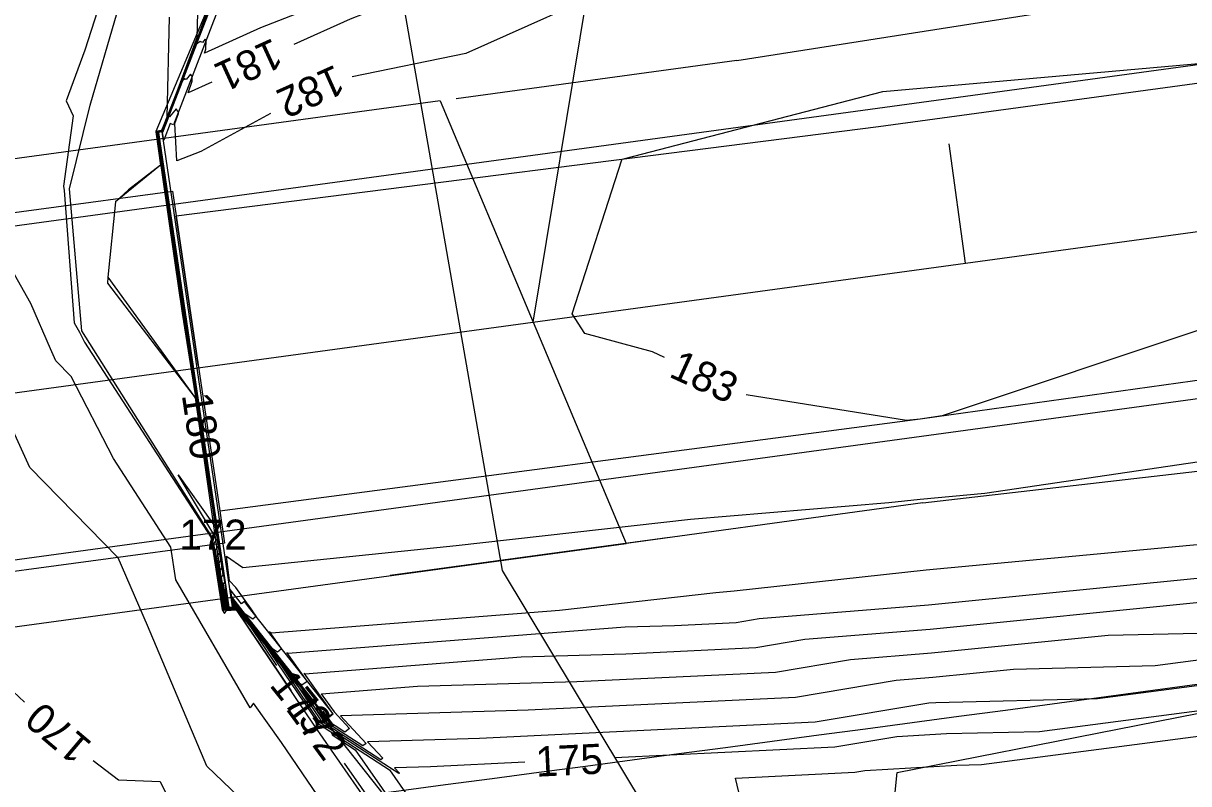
# Model space of a CAD drawing. Extents: x 2086416 to 2115205, y 575507 to 632762.
# Drawn here: x 2111557.3 to 2111634.8, y 581629.5 to 581680.1 of the extents above; entities that cross this region are included whole.
import ezdxf

# ---------------------------------------------------------------- set-up
doc = ezdxf.new("R2010")
doc.units = 0
for name, color, linetype in [('DTM Contours Major', 7, 'Continuous'), ('DTM Contours Major Text', 7, 'Continuous'), ('DTM Contours Minor', 7, 'Continuous'), ('DTM Contours Minor Text', 7, 'Continuous'), ('Exist Hydro Stream or Body of Water', 7, 'Continuous'), ('Exist Hydrographic Stream Bed', 7, 'Continuous'), ('Exist Right of Way Line', 7, 'Continuous'), ('Exist Roads EOP', 7, 'Continuous'), ('Exist Structure Major Bridge WW', 7, 'Continuous'), ('Exist Structure Major Deck Tunnel Box Culvert', 7, 'Continuous'), ('Exist Vegetation Woods Line', 7, 'Continuous'), ('Prop EOT', 7, 'Continuous'), ('Prop Horizontal Alignment', 7, 'Continuous'), ('Prop Horizontal Alignment Station Label', 7, 'Continuous'), ('Prop Horizontal Alignment Tick Large', 7, 'Continuous'), ('Prop Paved Shoulder', 7, 'Continuous'), ('Prop Roadway Bridge', 7, 'Continuous'), ('Prop SS Cut Line', 7, 'Continuous')]:
    doc.layers.add(name, color=color, linetype=linetype)

msp = doc.modelspace()

# ---------------------------------------------------------------- linework, layer by layer
at = {"layer": 'DTM Contours Major'}
for points in [[(2111577.062, 581633.567), (2111574.13, 581637.914), (2111571.386, 581641.335), (2111571.409, 581641.143), (2111571.336, 581641.132), (2111570.733, 581641.093), (2111570.186, 581644.597), (2111570.364, 581644.847), (2111569.098, 581653.407), (2111567.724, 581662.01), (2111566.227, 581672.465), (2111566.165, 581672.886), (2111566.466, 581672.935), (2111566.521, 581672.943), (2111566.528, 581672.934), (2111568.39, 581677.722), (2111570.775, 581684.171)], [(2111580.165, 581682.557), (2111573.082, 581679.801), (2111569.362, 581678.106), (2111569.457, 581678.372), (2111569.468, 581678.954), (2111569.404, 581679.039), (2111569.226, 581678.826), (2111569.08, 581678.891), (2111568.834, 581678.698), (2111566.565, 581672.861), (2111566.542, 581672.893), (2111566.359, 581672.866), (2111566.259, 581672.849), (2111566.467, 581671.443), (2111566.966, 581667.96), (2111567.423, 581665.095), (2111568.733, 581656.242)], [(2111563.624, 581644.535), (2111557.765, 581650.557), (2111554.83, 581656.943), (2111553.167, 581660.831), (2111550.584, 581662.207), (2111544.629, 581660.993), (2111538.463, 581666.005), (2111535.965, 581667.83), (2111530.949, 581672.288), (2111530.521, 581672.558), (2111527.53, 581672.834), (2111528.703, 581670.603), (2111528.883, 581668.916), (2111534.119, 581665.006), (2111537.381, 581653.906), (2111537.496, 581653.447), (2111544.432, 581648.303), (2111549.461, 581642.401), (2111557.401, 581634.942)], [(2111569.612, 581650.307), (2111570.775, 581642.449), (2111570.715, 581642.365), (2111570.897, 581641.201), (2111571.098, 581641.214), (2111571.287, 581641.242), (2111571.228, 581641.744)], [(2111571.228, 581641.744), (2111575.652, 581636.227), (2111575.847, 581636.099), (2111575.905, 581636.144), (2111576.193, 581636.349), (2111574.837, 581638.252), (2111574.911, 581638.195), (2111597.323, 581639.951), (2111600.607, 581640.048), (2111604.699, 581640.246), (2111606.241, 581640.505), (2111617.499, 581641.405), (2111642.062, 581643.861), (2111644.096, 581643.911), (2111647.513, 581644.36), (2111664.381, 581646.045)], [(2111561.972, 581631.067), (2111563.648, 581629.772), (2111566.428, 581629.67), (2111574.697, 581612.578), (2111574.966, 581612.195), (2111584.328, 581609.029), (2111586.691, 581607.388), (2111582.492, 581616.152), (2111576.474, 581624.007), (2111569.516, 581630.68), (2111565.57, 581640.043), (2111563.624, 581644.535)], [(2111696.049, 581641.363), (2111672.077, 581638.811), (2111669.843, 581638.828), (2111651.777, 581636.424), (2111648.999, 581636.147), (2111624.869, 581632.976), (2111618.681, 581632.825), (2111615.387, 581632.634), (2111611.27, 581631.941), (2111596.647, 581631.235)], [(2111590.654, 581630.945), (2111584.392, 581630.643), (2111581.999, 581630.572), (2111582.326, 581630.219), (2111582.283, 581630.187), (2111577.062, 581633.567)]]:
    msp.add_lwpolyline(points, dxfattribs=at)
at = {"layer": 'DTM Contours Minor'}
for points in [[(2111554.563, 581717.65), (2111557.36, 581715.394), (2111558.77, 581713.514), (2111570.458, 581698.119), (2111560.752, 581706.535), (2111561.783, 581697.351), (2111565.987, 581692.592), (2111561.42, 581678.299), (2111560.172, 581674.931), (2111560.629, 581673.945), (2111559.995, 581669.266), (2111560.03, 581668.962), (2111560.707, 581660.161), (2111561.06, 581659.542), (2111561.396, 581658.891), (2111569.796, 581645.905), (2111570.547, 581641.087), (2111570.686, 581640.847), (2111570.828, 581641.041), (2111571.479, 581641.083), (2111571.482, 581641.083), (2111571.481, 581641.089), (2111571.569, 581640.98), (2111575.135, 581635.693)], [(2111771.48, 581708.935), (2111760.551, 581707.387), (2111751.324, 581706.065), (2111741.049, 581703.184), (2111726.364, 581703.031), (2111711.255, 581700.898), (2111699.308, 581700.058), (2111691.644, 581698.037), (2111679.979, 581697.458), (2111663.055, 581697.517), (2111661.641, 581697.308), (2111661.538, 581697.284), (2111642.179, 581694.795), (2111641.925, 581694.737), (2111612.432, 581690.93), (2111612.349, 581690.915), (2111598.441, 581688.663), (2111596.352, 581688.299), (2111593.432, 581686.787), (2111582.067, 581681.437), (2111581.765, 581681.432), (2111579.054, 581680.377), (2111575.311, 581678.672)], [(2111775.952, 581702.182), (2111765.879, 581701.692), (2111760.907, 581700.977), (2111757.858, 581700.672), (2111741.952, 581696.212), (2111712.843, 581695.908), (2111712.055, 581695.797), (2111711.432, 581695.753), (2111692.466, 581690.751), (2111663.596, 581689.317), (2111662.082, 581689.322), (2111660.385, 581689.117), (2111642.993, 581686.483), (2111626.562, 581686.502), (2111613.936, 581684.954), (2111604.265, 581685.115), (2111597.651, 581682.972), (2111586.742, 581678.077), (2111579.19, 581676.523)], [(2111569.01, 581685.022), (2111568.855, 581679.129), (2111567.524, 581675.529), (2111566.521, 581672.948), (2111566.517, 581672.953), (2111566.487, 581672.949), (2111566.146, 581672.893), (2111566.179, 581672.67), (2111567.876, 581660.82), (2111569.433, 581651.069), (2111570.282, 581645.327), (2111570.08, 581645.043), (2111570.701, 581641.072), (2111571.384, 581641.115), (2111571.433, 581641.123), (2111571.418, 581641.253), (2111573.276, 581638.936), (2111576.945, 581633.496), (2111581.656, 581630.446), (2111583.793, 581627.386), (2111584.244, 581626.917), (2111585.478, 581625.384)], [(2111577.178, 581633.638), (2111574.983, 581636.892), (2111571.354, 581641.416), (2111571.385, 581641.163), (2111571.288, 581641.148), (2111570.766, 581641.115), (2111570.292, 581644.15), (2111570.446, 581644.368), (2111568.763, 581655.744), (2111567.573, 581663.2), (2111566.275, 581672.261), (2111566.184, 581672.878), (2111566.444, 581672.921), (2111566.525, 581672.933), (2111566.535, 581672.919), (2111569.255, 581679.915), (2111570.799, 581684.09)], [(2111577.411, 581633.781), (2111576.691, 581634.848), (2111571.291, 581641.58), (2111571.336, 581641.203), (2111571.193, 581641.181), (2111570.832, 581641.158), (2111570.504, 581643.258), (2111570.611, 581643.408), (2111568.093, 581660.42), (2111567.269, 581665.58), (2111566.371, 581671.852), (2111566.221, 581672.864), (2111566.402, 581672.893), (2111566.534, 581672.913), (2111566.55, 581672.89), (2111570.691, 581683.54)], [(2111577.294, 581633.709), (2111575.837, 581635.87), (2111571.323, 581641.498), (2111571.36, 581641.183), (2111571.241, 581641.165), (2111570.799, 581641.136), (2111570.398, 581643.704), (2111570.529, 581643.888), (2111568.428, 581658.082), (2111567.421, 581664.39), (2111566.323, 581672.056), (2111566.203, 581672.871), (2111566.423, 581672.907), (2111566.53, 581672.923), (2111566.543, 581672.905), (2111570.121, 581682.109)], [(2111576.272, 581682.839), (2111573.71, 581682.421), (2111570.375, 581681.023), (2111570.381, 581681.335), (2111570.364, 581681.358), (2111570.316, 581681.3), (2111570.109, 581681.392), (2111569.763, 581681.119), (2111566.558, 581672.876), (2111566.538, 581672.903), (2111566.381, 581672.879), (2111566.24, 581672.856), (2111566.419, 581671.647), (2111567.118, 581666.77), (2111567.758, 581662.757), (2111570.693, 581642.928), (2111570.61, 581642.812), (2111570.865, 581641.18), (2111571.145, 581641.198), (2111571.312, 581641.222), (2111571.26, 581641.662)], [(2111567.025, 581680.498), (2111566.851, 581673.856), (2111566.658, 581673.336), (2111566.513, 581672.963), (2111566.513, 581672.963), (2111566.508, 581672.963), (2111566.127, 581672.9), (2111566.131, 581672.874), (2111566.449, 581670.656), (2111564.307, 581669.018), (2111563.443, 581668.224), (2111562.943, 581663.213), (2111562.927, 581662.803), (2111568.739, 581655.173), (2111569.767, 581648.731), (2111570.2, 581645.807), (2111569.974, 581645.489), (2111570.668, 581641.05), (2111571.432, 581641.099), (2111571.457, 581641.103), (2111571.449, 581641.171), (2111572.422, 581639.958), (2111574.154, 581637.391)], [(2111643.847, 581677.764), (2111644.952, 581677.932), (2111662.194, 581679.764), (2111662.971, 581679.587), (2111663.56, 581679.562), (2111683.069, 581679.032), (2111693.952, 581679.325), (2111701.93, 581679.257), (2111713.811, 581679.697), (2111722.926, 581678.431), (2111717.299, 581676.654), (2111714.292, 581675.929), (2111711.547, 581675.446), (2111695.04, 581672.327), (2111687.453, 581670.987), (2111665.531, 581666.866), (2111655.863, 581664.226), (2111646.097, 581662.087), (2111636.124, 581659.903), (2111618.397, 581653.989), (2111616.941, 581653.759), (2111616.037, 581653.667), (2111605.38, 581655.386)], [(2111599.933, 581657.871), (2111599.142, 581658.247), (2111594.644, 581659.471), (2111593.813, 581660.769), (2111597.108, 581671.011), (2111597.122, 581671.059), (2111597.229, 581671.081), (2111597.239, 581671.086), (2111597.297, 581671.105), (2111614.462, 581675.567), (2111639.449, 581677.769), (2111643.847, 581677.764)], [(2111569.851, 581676.185), (2111568.274, 581675.467), (2111568.549, 581676.238), (2111568.556, 581676.573), (2111568.444, 581676.72), (2111568.136, 581676.352), (2111568.05, 581676.39), (2111567.906, 581676.276), (2111566.572, 581672.847), (2111566.547, 581672.883), (2111566.338, 581672.852), (2111566.278, 581672.842), (2111566.515, 581671.238), (2111566.814, 581669.15), (2111567.088, 581667.433), (2111570.857, 581641.969), (2111570.821, 581641.919), (2111570.93, 581641.223), (2111571.05, 581641.231), (2111571.263, 581641.262), (2111571.196, 581641.825)], [(2111573.759, 581674.096), (2111569.118, 581671.56), (2111567.528, 581670.942), (2111567.402, 581673.431), (2111567.641, 581674.104), (2111567.643, 581674.192), (2111567.484, 581674.402), (2111567.046, 581673.878), (2111567.021, 581673.889), (2111566.978, 581673.855), (2111566.58, 581672.832), (2111566.551, 581672.873), (2111566.317, 581672.838), (2111566.297, 581672.835), (2111566.563, 581671.034), (2111566.662, 581670.341), (2111566.753, 581669.77), (2111570.939, 581641.489), (2111570.927, 581641.473), (2111570.963, 581641.244), (2111571.002, 581641.247), (2111571.239, 581641.282), (2111571.165, 581641.907)], [(2111598.535, 581596.664), (2111585.912, 581617.09), (2111584.535, 581618.974), (2111576.895, 581628.719), (2111574.477, 581632.249), (2111572.617, 581634.865), (2111572.402, 581634.572), (2111567.467, 581643.071), (2111567.127, 581645.256), (2111563.317, 581651.146), (2111560.505, 581656.601), (2111559.492, 581657.643), (2111559.123, 581658.446), (2111557.832, 581661.464), (2111555.517, 581665.512)], [(2111571.165, 581641.907), (2111571.996, 581640.87), (2111572.571, 581640.492), (2111572.743, 581640.626), (2111572.795, 581640.663), (2111572.546, 581641.013), (2111572.584, 581640.984), (2111571.455, 581642.576), (2111571.032, 581643.012), (2111570.823, 581644.648), (2111571.916, 581643.904), (2111586.094, 581645.355), (2111601.664, 581647.121), (2111614.846, 581648.211), (2111616.947, 581648.442), (2111621.236, 581648.843), (2111646.92, 581652.625), (2111665.944, 581653.445), (2111667.701, 581653.608), (2111692.097, 581649.43)], [(2111569.975, 581646.085), (2111567.608, 581650.059), (2111569.849, 581646.913), (2111570.065, 581646.63), (2111570.102, 581646.394), (2111570.118, 581646.287), (2111569.975, 581646.085)], [(2111571.196, 581641.825), (2111573.824, 581638.549), (2111574.209, 581638.295), (2111574.324, 581638.385), (2111574.494, 581638.506), (2111573.692, 581639.632), (2111573.792, 581639.556), (2111592.953, 581641.057), (2111603.347, 581642.235), (2111604.567, 581642.336), (2111617.335, 581643.741), (2111643.391, 581646.181), (2111647.216, 581646.744), (2111650.05, 581646.866), (2111668.074, 581648.539), (2111670.919, 581648.052), (2111693.464, 581647.881)], [(2111571.26, 581641.662), (2111577.48, 581633.906), (2111577.485, 581633.903), (2111577.486, 581633.904), (2111577.892, 581634.191), (2111575.982, 581636.871), (2111576.03, 581636.835), (2111590.423, 581637.963), (2111597.364, 581638.167), (2111606.013, 581638.585), (2111609.271, 581639.133), (2111617.594, 581639.798), (2111635.752, 581641.614), (2111640.25, 581641.724), (2111647.81, 581642.717), (2111662.919, 581644.226), (2111668.671, 581644.992), (2111686.335, 581644.858)], [(2111671.884, 581640.351), (2111669.55, 581640.369), (2111654.563, 581638.375), (2111648.702, 581637.79), (2111628.715, 581635.163), (2111617.979, 581634.901), (2111617.512, 581634.874), (2111609.956, 581633.602), (2111587.635, 581632.524), (2111580.203, 581632.305), (2111581.22, 581631.207), (2111581.086, 581631.108), (2111577.178, 581633.638)], [(2111638.154, 581639.767), (2111636.405, 581639.537), (2111629.442, 581639.367), (2111617.689, 581638.192), (2111612.302, 581637.761), (2111607.327, 581636.924), (2111594.121, 581636.286), (2111583.523, 581635.974), (2111577.149, 581635.474), (2111577.128, 581635.491), (2111577.984, 581634.288), (2111579.007, 581633.185), (2111578.692, 581632.951), (2111577.411, 581633.781)], [(2111655.217, 581640.113), (2111648.405, 581639.432), (2111632.56, 581637.35), (2111623.132, 581637.12), (2111617.784, 581636.585), (2111615.332, 581636.39), (2111608.642, 581635.263), (2111590.878, 581634.405), (2111578.406, 581634.038), (2111580.113, 581632.196), (2111579.889, 581632.029), (2111577.294, 581633.709)], [(2111589.242, 581620.711), (2111589.877, 581619.921), (2111590.857, 581618.927), (2111592.405, 581618.486), (2111599.33, 581615.104), (2111605.372, 581623.887), (2111605.711, 581625.528), (2111604.66, 581629.897), (2111612.584, 581630.28), (2111613.262, 581630.394), (2111619.383, 581630.749), (2111621.024, 581630.789), (2111642.89, 581633.662), (2111647.196, 581633.15), (2111648.463, 581631.541), (2111653.203, 581633.039), (2111670.864, 581631.971), (2111682.196, 581631.349), (2111685.064, 581615.457), (2111702.133, 581615.465), (2111706.656, 581602.934), (2111726.967, 581593.524), (2111719.652, 581583.63), (2111725.706, 581574.006)], [(2111577.85, 581632.764), (2111579.379, 581631.774), (2111585.586, 581622.885), (2111586.895, 581621.522), (2111588.77, 581619.193), (2111592.833, 581615.071), (2111599.247, 581613.245), (2111610.211, 581607.891), (2111612.256, 581606.571), (2111617.699, 581603.706), (2111619.118, 581601.942), (2111619.518, 581603.35), (2111619.215, 581603.582), (2111621.458, 581611.664), (2111622.113, 581614.012), (2111639.991, 581603.538), (2111640.806, 581603.356), (2111642.077, 581602.394), (2111666.164, 581595.53), (2111674.849, 581575.034)], [(2111578.656, 581630.876), (2111587.378, 581618.383), (2111587.912, 581617.828), (2111588.893, 581616.777), (2111596.136, 581605.984), (2111600.862, 581598.818)]]:
    msp.add_lwpolyline(points, dxfattribs=at)
at = {"layer": 'Exist Hydro Stream or Body of Water'}
msp.add_lwpolyline([(2111621.041, 581592.195), (2111611.64, 581604.325), (2111605.912, 581608.14), (2111600.475, 581607.014), (2111602.119, 581600.097), (2111601.107, 581599.205), (2111587.776, 581617.384), (2111576.692, 581633.341), (2111571.484, 581641.081), (2111570.636, 581641.029), (2111569.871, 581645.923), (2111561.21, 581659.642), (2111560.398, 581669.08), (2111561.77, 581674.655), (2111567.139, 581693.151), (2111571.775, 581696.534), (2111557.095, 581714.198)], dxfattribs=at)
at = {"layer": 'Exist Hydrographic Stream Bed'}
msp.add_lwpolyline([(2112129.652, 582477.712), (2111835.899, 582368.961), (2111727.147, 582231.15), (2111672.647, 582129.589), (2111610.896, 582009.957), (2111585.646, 581897.526), (2111574.646, 581806.895), (2111574.646, 581727.084), (2111582.896, 581679.524), (2111589.146, 581643.704), (2111621.896, 581589.333), (2111665.397, 581516.772), (2111701.647, 581379.011), (2111737.898, 581248.45), (2111785.148, 581103.388)], dxfattribs=at)
at = {"layer": 'Exist Right of Way Line'}
msp.add_arc((2108326.546, 606231.499), 24816.937, 277.3939111, 277.8562149, dxfattribs=at)
at = {"layer": 'Exist Roads EOP'}
for points in [[(2111568.946, 581657.382), (2111567.482, 581667.278), (2111614.169, 581673.234), (2111663.501, 581679.942), (2111712.967, 581686.457), (2111762.009, 581693.34), (2111810.989, 581700.16), (2111860.082, 581706.99), (2111909.436, 581713.775), (2111958.293, 581720.29), (2112007.473, 581726.809), (2112052.556, 581733.019), (2112053.866, 581723.651)], [(2111568.946, 581657.382), (2111567.482, 581667.278), (2111614.169, 581673.234), (2111663.501, 581679.942), (2111712.967, 581686.457), (2111762.009, 581693.34), (2111810.989, 581700.16), (2111860.082, 581706.99), (2111909.436, 581713.775), (2111958.293, 581720.29), (2112007.473, 581726.809), (2112052.556, 581733.019), (2112053.866, 581723.651)], [(2111568.946, 581657.382), (2111570.384, 581647.665), (2111616.941, 581653.786), (2111666.479, 581660.703), (2111715.395, 581667.634), (2111764.576, 581674.503), (2111813.386, 581681.192), (2111862.599, 581687.866), (2111911.635, 581694.622), (2111960.562, 581701.229), (2112009.92, 581707.698), (2112055.279, 581713.547), (2112053.866, 581723.651)]]:
    msp.add_lwpolyline(points, dxfattribs=at)
at = {"layer": 'Exist Structure Major Bridge WW'}
for points in [[(2111566.583, 581672.826), (2111566.849, 581673.52), (2111570.25, 581682.39), (2111570.844, 581683.94), (2111571.077, 581683.851), (2111570.483, 581682.3), (2111570.717, 581682.211), (2111567.316, 581673.341), (2111567.082, 581673.43), (2111566.658, 581672.322), (2111566.583, 581672.826)], [(2111566.553, 581672.868), (2111566.306, 581672.831), (2111570.979, 581641.255), (2111571.227, 581641.292), (2111566.553, 581672.868)], [(2111571.15, 581641.945), (2111571.908, 581640.981), (2111577.524, 581633.85), (2111577.917, 581634.159), (2111572.301, 581641.291), (2111572.031, 581641.634), (2111571.834, 581641.48), (2111571.075, 581642.444), (2111571.15, 581641.945)]]:
    msp.add_lwpolyline(points, dxfattribs=at)
at = {"layer": 'Exist Structure Major Deck Tunnel Box Culvert'}
msp.add_lwpolyline([(2111518.338, 581638.473), (2111518.005, 581640.729), (2111516.542, 581650.631), (2111515.092, 581660.442), (2111514.879, 581661.883), (2111532.718, 581664.281), (2111549.455, 581666.531), (2111567.238, 581668.922), (2111567.482, 581667.278), (2111568.946, 581657.382), (2111570.384, 581647.665), (2111570.703, 581645.511), (2111552.911, 581643.12), (2111536.107, 581640.862), (2111518.338, 581638.473)], dxfattribs=at)
at = {"layer": 'Exist Vegetation Woods Line'}
msp.add_lwpolyline([(2111779.567, 581491.973), (2111763.785, 581504.851), (2111745.339, 581525.059), (2111717.304, 581555.588), (2111690.346, 581575.953), (2111665.09, 581587.143), (2111644.347, 581594.336), (2111622.456, 581605.396), (2111614.175, 581617.919), (2111615.41, 581630.255), (2111644.692, 581636.018), (2111711.675, 581643.899), (2111763.228, 581655.57), (2111785.51, 581656)], dxfattribs=at)
at = {"layer": 'Prop EOT'}
for p, q in [((2111430.061, 581649.328), (2112312.029, 581769.688)), ((2111433.036, 581627.53), (2112315.004, 581747.89))]:
    msp.add_line(p, q, dxfattribs=at)
at = {"layer": 'Prop Horizontal Alignment'}
msp.add_line((2111431.548, 581638.429), (2112404.465, 581771.2), dxfattribs=at)
at = {"layer": 'Prop Horizontal Alignment Station Label'}
msp.add_line((2111591.211, 581660.217), (2111612.471, 581789.237), dxfattribs=at)
at = {"layer": 'Prop Horizontal Alignment Tick Large'}
msp.add_line((2111619.945, 581664.139), (2111618.863, 581672.065), dxfattribs=at)
at = {"layer": 'Prop Paved Shoulder'}
for p, q in [((2111604.761, 581677.626), (2111633.584, 581682.148)), ((2111604.761, 581677.626), (2111586.084, 581675.077)), ((2111617.116, 581648.193), (2111646.097, 581651.559)), ((2111617.116, 581648.193), (2111593.197, 581644.929)), ((2111600.281, 581645.896), (2111581.703, 581643.36))]:
    msp.add_line(p, q, dxfattribs=at)
at = {"layer": 'Prop Roadway Bridge'}
for p, q in [((2111585.034, 581674.934), (2111495.86, 581662.765)), ((2111585.034, 581674.934), (2111597.389, 581645.501)), ((2111508.215, 581633.332), (2111597.389, 581645.501))]:
    msp.add_line(p, q, dxfattribs=at)
at = {"layer": 'Prop SS Cut Line'}
for p, q in [((2111570.02, 581682.16), (2111566.127, 581672.9)), ((2111566.127, 581672.9), (2111566.449, 581670.656)), ((2111566.449, 581670.656), (2111563.443, 581668.224)), ((2111563.443, 581668.224), (2111562.943, 581663.213)), ((2111562.943, 581663.213), (2111568.739, 581655.173)), ((2111568.739, 581655.173), (2111570.766, 581641.115)), ((2111570.766, 581641.115), (2111571.503, 581641.14)), ((2111571.503, 581641.14), (2111582.793, 581626.876))]:
    msp.add_line(p, q, dxfattribs=at)

# ---------------------------------------------------------------- texts
at = {"layer": 'DTM Contours Major Text'}
for s, rotation, p in [('180', 278.41848, (2111567.85, 581655.379)), ('170', 139.71038, (2111561.981, 581632.192)), ('175', 2.76607, (2111591.426, 581629.981))]:
    msp.add_text(s, height=2, rotation=rotation, dxfattribs=at).set_placement(p)
at = {"layer": 'DTM Contours Minor Text'}
for s, rotation, p in [('181', 204.48892, (2111573.929, 581679.142)), ('182', 204.08493, (2111578.062, 581677.376)), ('183', 335.47756, (2111600.157, 581656.617)), ('173', 308.61859, (2111573.63, 581636.058)), ('172', 306.16573, (2111574.713, 581634.504))]:
    msp.add_text(s, height=2, rotation=rotation, dxfattribs=at).set_placement(p)
msp.add_text('172', height=2, dxfattribs=at).set_placement((2111567.699, 581645.085))

doc.saveas('drawing.dxf')
